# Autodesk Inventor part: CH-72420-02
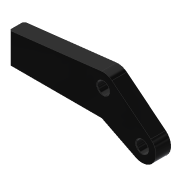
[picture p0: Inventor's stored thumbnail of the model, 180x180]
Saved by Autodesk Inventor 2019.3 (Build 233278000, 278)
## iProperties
Created: 2013-06
Part Number: CH-72420-02
Material: Ogólny
Document SubType Name: Modeling
Designer: CADENGINEERING4
Density: 1 g/cm^3
Appearance: Gładki — czarny
Author: CADENGINEERING4
Revision Number: ÈÎºÎ
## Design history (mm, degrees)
feature "ÊäÈë1"
node "Bryła1"
